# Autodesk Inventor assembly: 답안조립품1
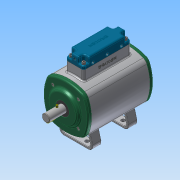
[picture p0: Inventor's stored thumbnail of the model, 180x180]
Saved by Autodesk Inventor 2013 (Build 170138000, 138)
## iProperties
Created: 2016-10
Part Number: 답안조립품1
Document SubType Name: Assembly
Designer: Administrator
Mass: 3565.93 g
Surface Area: 2672.9 cm^2
Volume: 917.884 cm^3
Density: 3.88494 g/cm^3
Author: Administrator
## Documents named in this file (18)
- C:\Users\Administrator\Desktop\361008V1006\답안조립품1.iam
- C:\Users\Administrator\Desktop\361008V1006\본체.ipt
- C:\Users\Administrator\Desktop\361008V1006\축.ipt
- C:\Users\Administrator\Desktop\361008V1006\V-벨트풀리.ipt
- C:\Users\Administrator\Desktop\361008V1006\멈춤나사 M4x5.ipt
- C:\Users\Administrator\Desktop\361008V1006\키 - 5 x 5 x 18.ipt
- C:\Users\Administrator\Desktop\361008V1006\오일실 17 30 8.ipt
- C:\Users\Administrator\Desktop\361008V1006\뒷커버.ipt
- C:\Users\Administrator\Desktop\361008V1006\앞커버.ipt
- C:\Users\Administrator\Desktop\361008V1006\베어링 6203.ipt
- C:\Users\Administrator\Desktop\361008V1006\볼트 M4 x 12.ipt
- C:\Users\Administrator\Desktop\361008V1006\슬라이드.ipt
- C:\Users\Administrator\Desktop\361008V1006\부시.ipt
- C:\Users\Administrator\Desktop\361008V1006\스프링3.ipt
- C:\Users\Administrator\Desktop\361008V1006\스프링1.ipt
- C:\Users\Administrator\Desktop\361008V1006\스프링2.ipt
- C:\Users\Administrator\Desktop\361008V1006\헤더커버.ipt
- C:\Users\Administrator\Desktop\361008V1006\볼트 M4 x 16.ipt
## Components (4 placed, 3 different names)
1. V-벨트풀리:1 — 플러쉬:1
2. 7-베어링 6203:1
3. 7-베어링 6203:2
4. 헤더커버:1
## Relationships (1: Flush 1)
- 플러쉬:1 [Flush]: V-벨트풀리:1
